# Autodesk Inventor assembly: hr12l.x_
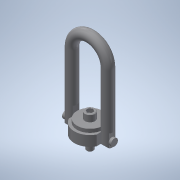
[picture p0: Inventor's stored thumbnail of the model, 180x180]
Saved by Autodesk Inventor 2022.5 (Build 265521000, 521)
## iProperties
Part Number: hr12l.x_
Material: 一般
Document SubType Name: Assembly
Designer: ImaoCorp
Sending System: SOLIDWORKS 2017-2017317
MC: AMD64
MC_MODEL: Intel64 Family 6 Model 60 Stepping 3, GenuineIntel
OS: Windows_NT
FRU: Parasolid Version 29.0, build 201,  4-17-2017
FORMAT: text
GUISE: transmit
KEY: hr12l
FILE: hr12l.x_t
DATE: Mon Jul 01 17:37:19 2019
Author: ImaoCorp
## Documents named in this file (3)
- X:\14_SW2022-Inv2022\00_全2023-1023新製品(TCC)まで\h\hr12l\HR12L.iam
- X:\14_SW2022-Inv2022\00_全2023-1023新製品(TCC)まで\h\hr12l\hr12l_01.ipt
- X:\14_SW2022-Inv2022\00_全2023-1023新製品(TCC)まで\h\hr12l\hr12l_02.ipt
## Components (2 placed, 2 different names)
1. hr12l_01
2. hr12l_02
